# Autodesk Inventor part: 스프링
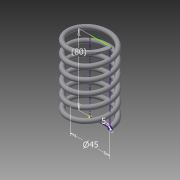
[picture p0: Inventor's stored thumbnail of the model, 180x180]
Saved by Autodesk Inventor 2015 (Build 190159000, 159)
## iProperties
Created: 2015-10
Part Number: 스프링
Material: Generic
Document SubType Name: Modeling
Designer: youjin03
Density: 1 g/cm^3
Appearance: Default
Author: youjin03
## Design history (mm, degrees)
sketch "Sketch1"
  geometry: L1 (-22.5, 80)-(0, 80); L2 (0, 80)-(0, 0); L3 (0, 0)-(-22.5, 0); L4 (-22.5, 0)-(-22.5, 80); C1 r 2.5 at (-22.5, 0); 1 further point
  constraints: 8 end point, 2 coincident, 2 parallel, 1 centre point, 1 horizontal, 1 perpendicular
  dimensions: "d0" = 80 distance between parallel lines of L1 L3 (derived); "d1" = 45 diameter of L4 L2; "d2" = 5 diameter of C1
coil "Coil1" sketch "Sketch1" pitch "d3" = 10; turns "d5" = 6; dims "d4" = 80 (= d0), "d6" = 0, angle "d7" = 90 deg, angle "d8" = 90 deg, "d9" = 0, "d10" = 0
sketch "Sketch2"
  geometry: L1 (25, 0)-(20, 0) reference; 1 further point
  constraints: 1 horizontal alignment
extrude "Extrusion1" cut sketch "Sketch2" stored distance "d11" = 10; taper "d12" = 0 deg
workplane "Work Plane1"
sketch "Sketch3"
  geometry: L1 (-25, 0)-(-20, 0) reference; 1 further point
  constraints: 1 horizontal alignment
extrude "Extrusion2" cut sketch "Sketch3" stored distance "d13" = 10; taper "d14" = 0 deg
body "Solid1"
node "Project Cut Edges1"
node "Project Cut Edges2"
